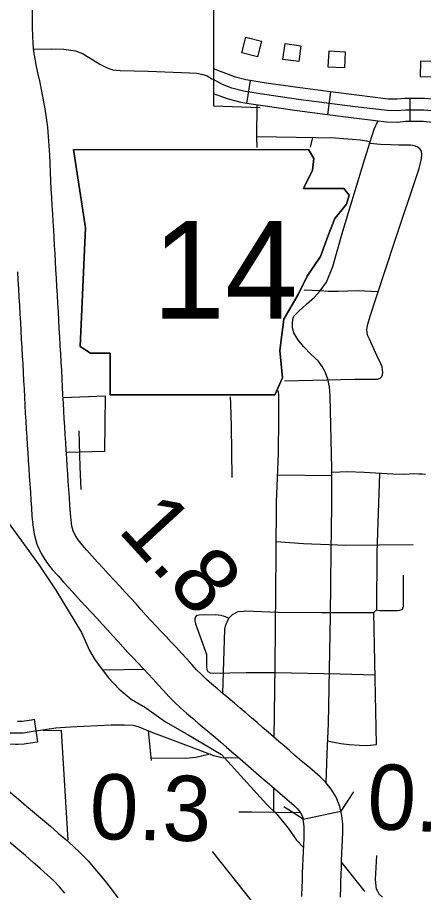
# Model space of a CAD drawing. Extents: x 1370130 to 1380143, y 377636 to 380256.
# Drawn here: x 1377398.1 to 1377471.8, y 379033.5 to 379192.2 of the extents above; entities that cross this region are included whole.
import ezdxf

# ---------------------------------------------------------------- set-up
doc = ezdxf.new("R2010")
doc.units = 0
for name, color, linetype in [('Level 10', 7, 'Continuous'), ('Level 15', 7, 'Continuous'), ('Level 21', 7, 'Continuous'), ('Level 31', 7, 'Continuous'), ('Level 32', 7, 'Continuous'), ('Level 33', 7, 'Continuous'), ('Level 34', 7, 'Continuous'), ('Level 35', 7, 'Continuous'), ('Level 37', 7, 'Continuous'), ('Level 48', 7, 'Continuous'), ('Level 49', 7, 'Continuous'), ('Level 56', 7, 'Continuous'), ('Level 6', 7, 'Continuous')]:
    doc.layers.add(name, color=color, linetype=linetype)

msp = doc.modelspace()

# ---------------------------------------------------------------- linework, layer by layer
at = {"layer": 'Level 10'}
for p, q in [((1377399.47, 379121.9), (1377399.48, 379121.89)), ((1377406.46, 379122.28), (1377406.46, 379122.27)), ((1377449.98, 379046.79), (1377456.82, 379048.25))]:
    msp.add_line(p, q, dxfattribs=at)
for points in [[(1377406.46, 379122.27), (1377406.39, 379123.72), (1377406.32, 379125.18), (1377406.24, 379126.67), (1377406.16, 379128.17), (1377406.08, 379129.68), (1377406, 379131.19), (1377405.91, 379132.73), (1377405.82, 379134.25), (1377405.73, 379135.77), (1377405.65, 379137.29), (1377405.56, 379138.8), (1377405.48, 379140.34), (1377405.39, 379141.88), (1377405.3, 379143.39), (1377405.21, 379144.93), (1377405.12, 379146.47), (1377405.03, 379147.96), (1377404.95, 379149.41), (1377404.87, 379150.84), (1377404.8, 379152.25), (1377404.72, 379153.69), (1377404.63, 379155.13), (1377404.54, 379156.57), (1377404.45, 379158.03), (1377404.36, 379159.51), (1377404.27, 379161.03), (1377404.17, 379162.54), (1377404.1, 379164.07), (1377404.04, 379165.64), (1377403.98, 379167.26), (1377403.9, 379168.9), (1377403.79, 379170.59), (1377403.62, 379172.3), (1377403.4, 379173.98), (1377403.14, 379175.61), (1377402.87, 379177.21), (1377402.57, 379178.81), (1377402.23, 379180.41), (1377401.87, 379181.91), (1377401.57, 379183.3), (1377401.32, 379184.67), (1377401.12, 379186.03), (1377400.99, 379187.4), (1377400.92, 379188.83), (1377400.89, 379190.36), (1377400.89, 379191.97), (1377400.89, 379193.65)], [(1377398.14, 379146.05), (1377398.22, 379144.53), (1377398.31, 379142.98), (1377398.41, 379141.47), (1377398.49, 379139.95), (1377398.57, 379138.42), (1377398.66, 379136.89), (1377398.74, 379135.37), (1377398.83, 379133.85), (1377398.92, 379132.33), (1377399.01, 379130.8), (1377399.09, 379129.3), (1377399.17, 379127.79), (1377399.25, 379126.3), (1377399.33, 379124.83), (1377399.4, 379123.36), (1377399.47, 379121.9)], [(1377399.48, 379121.89), (1377399.56, 379120.44), (1377399.64, 379118.98), (1377399.73, 379117.52), (1377399.83, 379116.1), (1377399.92, 379114.69), (1377400.01, 379113.27), (1377400.1, 379111.85), (1377400.19, 379110.43), (1377400.28, 379109), (1377400.38, 379107.55), (1377400.48, 379106.11), (1377400.58, 379104.68), (1377400.67, 379103.24), (1377400.77, 379101.78), (1377400.9, 379100.21), (1377401.15, 379098.52), (1377401.65, 379096.7), (1377402.45, 379094.96), (1377403.42, 379093.43), (1377404.46, 379092.08), (1377405.49, 379090.91), (1377406.49, 379089.8), (1377407.51, 379088.69), (1377408.52, 379087.58), (1377409.54, 379086.48), (1377410.56, 379085.38), (1377411.57, 379084.29), (1377412.56, 379083.23), (1377413.53, 379082.18), (1377414.47, 379081.14), (1377415.39, 379080.11), (1377416.32, 379079.08), (1377417.25, 379078.06), (1377418.17, 379077.06), (1377419.1, 379076.07), (1377420.01, 379075.1), (1377420.93, 379074.13), (1377421.85, 379073.16), (1377422.75, 379072.18), (1377423.67, 379071.17), (1377424.61, 379070.14), (1377425.59, 379069.08), (1377426.64, 379068.02), (1377427.73, 379066.99), (1377428.81, 379066.03), (1377429.88, 379065.1), (1377430.95, 379064.2), (1377432, 379063.32), (1377433.03, 379062.46), (1377434.04, 379061.6), (1377435.04, 379060.75), (1377436.05, 379059.89), (1377437.05, 379059.02), (1377438.04, 379058.17), (1377439.03, 379057.32), (1377440, 379056.48), (1377440.96, 379055.63), (1377441.92, 379054.8), (1377442.88, 379053.96), (1377443.84, 379053.13), (1377444.81, 379052.3), (1377445.77, 379051.51), (1377446.67, 379050.76), (1377447.52, 379050.04), (1377448.28, 379049.37), (1377448.91, 379048.73), (1377449.39, 379048.17), (1377449.69, 379047.67), (1377449.91, 379047.11), (1377449.98, 379046.79)], [(1377456.82, 379048.25), (1377456.64, 379049.12), (1377455.99, 379050.8), (1377455.07, 379052.28), (1377454.07, 379053.47), (1377453.09, 379054.46), (1377452.11, 379055.33), (1377451.16, 379056.13), (1377450.24, 379056.9), (1377449.32, 379057.66), (1377448.41, 379058.44), (1377447.47, 379059.25), (1377446.52, 379060.08), (1377445.56, 379060.91), (1377444.59, 379061.76), (1377443.6, 379062.61), (1377442.62, 379063.46), (1377441.62, 379064.32), (1377440.62, 379065.19), (1377439.6, 379066.07), (1377438.57, 379066.95), (1377437.53, 379067.82), (1377436.49, 379068.69), (1377435.46, 379069.56), (1377434.43, 379070.42), (1377433.42, 379071.3), (1377432.45, 379072.16), (1377431.54, 379073.02), (1377430.65, 379073.92), (1377429.76, 379074.88), (1377428.84, 379075.89), (1377427.91, 379076.91), (1377426.97, 379077.93), (1377426.03, 379078.93), (1377425.11, 379079.91), (1377424.19, 379080.87), (1377423.29, 379081.83), (1377422.4, 379082.79), (1377421.51, 379083.77), (1377420.6, 379084.79), (1377419.66, 379085.83), (1377418.69, 379086.9), (1377417.7, 379087.98), (1377416.7, 379089.06), (1377415.69, 379090.14), (1377414.68, 379091.23), (1377413.66, 379092.33), (1377412.66, 379093.42), (1377411.67, 379094.5), (1377410.72, 379095.56), (1377409.86, 379096.54), (1377409.15, 379097.45), (1377408.61, 379098.3), (1377408.25, 379099.1), (1377408.01, 379099.96), (1377407.86, 379101.02), (1377407.75, 379102.3), (1377407.66, 379103.69), (1377407.56, 379105.14), (1377407.46, 379106.6), (1377407.36, 379108.02), (1377407.27, 379109.45), (1377407.18, 379110.88), (1377407.09, 379112.29), (1377407, 379113.71), (1377406.91, 379115.12), (1377406.82, 379116.56), (1377406.72, 379117.99), (1377406.63, 379119.41), (1377406.55, 379120.84), (1377406.46, 379122.28)], [(1377456.75, 379032.66), (1377456.76, 379032.95), (1377456.79, 379034.23), (1377456.83, 379035.51), (1377456.87, 379036.8), (1377456.91, 379038.07), (1377456.96, 379039.32), (1377457.01, 379040.56), (1377457.07, 379041.81), (1377457.13, 379043.09), (1377457.17, 379044.44), (1377457.15, 379045.91), (1377456.99, 379047.47), (1377456.82, 379048.25)], [(1377449.75, 379032.77), (1377449.76, 379033.11), (1377449.79, 379034.41), (1377449.83, 379035.72), (1377449.87, 379037.02), (1377449.91, 379038.32), (1377449.96, 379039.6), (1377450.02, 379040.88), (1377450.08, 379042.14), (1377450.13, 379043.37), (1377450.17, 379044.49), (1377450.15, 379045.5), (1377450.06, 379046.39), (1377449.98, 379046.79)]]:
    msp.add_lwpolyline(points, dxfattribs=at)
at = {"layer": 'Level 15'}
for points in [[(1377387.89, 379059.09), (1377389.38, 379057.86), (1377390.87, 379056.62), (1377392.37, 379055.38), (1377393.86, 379054.14), (1377395.36, 379052.9), (1377396.85, 379051.66), (1377398.32, 379050.41), (1377399.78, 379049.18), (1377401.24, 379047.96), (1377402.69, 379046.74), (1377404.14, 379045.52), (1377405.55, 379044.29), (1377406.9, 379043.1), (1377408.23, 379041.91), (1377409.6, 379040.66), (1377410.95, 379039.27), (1377412.11, 379037.89), (1377413.21, 379036.58), (1377414.28, 379035.25), (1377415.33, 379033.92), (1377416.34, 379032.57)], [(1377406.74, 379033.39), (1377405.75, 379034.57), (1377404.72, 379035.63), (1377403.54, 379036.72), (1377402.26, 379037.86), (1377400.93, 379039.03), (1377399.58, 379040.21), (1377398.19, 379041.38), (1377396.74, 379042.59), (1377395.27, 379043.82), (1377393.81, 379045.06), (1377392.35, 379046.29), (1377390.88, 379047.52), (1377389.39, 379048.75), (1377387.9, 379049.99), (1377386.4, 379051.23), (1377384.92, 379052.46), (1377383.43, 379053.69)]]:
    msp.add_lwpolyline(points, dxfattribs=at)
at = {"layer": 'Level 21'}
for p, q in [((1377408.33, 379168.25), (1377410.46, 379154.04)), ((1377451.91, 379166.6), (1377450.93, 379168.23)), ((1377451.68, 379164.47), (1377451.91, 379166.6)), ((1377450.02, 379161.15), (1377451.68, 379164.47)), ((1377457.36, 379161.15), (1377450.02, 379161.15)), ((1377458.31, 379159.97), (1377457.36, 379161.15)), ((1377457.84, 379158.31), (1377458.31, 379159.97)), ((1377455.7, 379155.7), (1377457.84, 379158.31)), ((1377454.52, 379152.62), (1377455.7, 379155.7)), ((1377410.46, 379154.04), (1377409.52, 379132.49)), ((1377453.1, 379148.83), (1377454.52, 379152.62)), ((1377450.73, 379145.28), (1377453.1, 379148.83)), ((1377449.07, 379141.96), (1377450.73, 379145.28)), ((1377446.47, 379137.46), (1377449.07, 379141.96)), ((1377445.76, 379131.78), (1377446.47, 379137.46)), ((1377409.52, 379132.49), (1377411.41, 379131.31)), ((1377411.41, 379131.31), (1377414.97, 379131.31)), ((1377414.97, 379131.31), (1377414.97, 379123.73)), ((1377446.23, 379126.81), (1377445.76, 379131.78)), ((1377444.81, 379123.73), (1377446.23, 379126.81)), ((1377414.97, 379123.73), (1377444.81, 379123.73))]:
    msp.add_line(p, q, dxfattribs=at)
msp.add_lwpolyline([(1377408.33, 379168.25), (1377450.93, 379168.23)], dxfattribs=at)
at = {"layer": 'Level 31'}
msp.add_line((1377401.16, 379064.92), (1377401.75, 379060.76), dxfattribs=at)
for points in [[(1377398.14, 379064.57), (1377398.96, 379064.59), (1377400.66, 379064.85), (1377401.16, 379064.92)], [(1377383.43, 379062.74), (1377385.49, 379062.53), (1377388.41, 379062.49), (1377390.94, 379062.57), (1377395.24, 379062.49), (1377397.77, 379062.45), (1377399.15, 379062.49), (1377400.96, 379062.77), (1377401.46, 379062.84)], [(1377401.75, 379060.76), (1377401.27, 379060.69), (1377399.34, 379060.4), (1377398.26, 379060.37)], [(1377398.26, 379060.37), (1377397.78, 379060.35), (1377395.2, 379060.39), (1377390.95, 379060.47), (1377388.43, 379060.39), (1377386.24, 379060.42)]]:
    msp.add_lwpolyline(points, dxfattribs=at)
at = {"layer": 'Level 32'}
for p, q in [((1377440.36, 379180.75), (1377439.71, 379176.6)), ((1377454.94, 379178.69), (1377454.4, 379174.53)), ((1377469.36, 379177.5), (1377469.36, 379173.3))]:
    msp.add_line(p, q, dxfattribs=at)
for points in [[(1377440.36, 379180.75), (1377439.6, 379180.87), (1377437.68, 379181.36), (1377433.7, 379182.84), (1377433.69, 379178.36)], [(1377484.13, 379174.88), (1377477.62, 379175), (1377474.11, 379175.2), (1377471.88, 379175.4), (1377470.16, 379175.4), (1377468.52, 379175.4), (1377467.04, 379175.25), (1377465.26, 379175.3), (1377459.43, 379175.99), (1377449.15, 379177.33), (1377442.98, 379178.22), (1377439.17, 379178.81), (1377437.05, 379179.35), (1377435.32, 379180), (1377433.7, 379180.91)], [(1377454.94, 379178.69), (1377449.44, 379179.41), (1377443.29, 379180.29), (1377440.36, 379180.75)], [(1377439.71, 379176.6), (1377438.75, 379176.75), (1377436.42, 379177.35), (1377433.69, 379178.36)], [(1377469.36, 379177.5), (1377468.42, 379177.5), (1377466.97, 379177.35), (1377465.42, 379177.39), (1377459.69, 379178.07), (1377454.94, 379178.69)], [(1377454.4, 379174.53), (1377448.87, 379175.24), (1377442.67, 379176.14), (1377439.71, 379176.6)], [(1377479.53, 379172.87), (1377479.54, 379177.07), (1377477.7, 379177.1), (1377474.26, 379177.29), (1377471.98, 379177.5), (1377470.16, 379177.5), (1377469.36, 379177.5)], [(1377469.36, 379173.3), (1377468.63, 379173.3), (1377467.12, 379173.15), (1377465.11, 379173.2), (1377459.17, 379173.91), (1377454.4, 379174.53)], [(1377479.53, 379172.87), (1377477.54, 379172.9), (1377473.96, 379173.1), (1377471.79, 379173.3), (1377470.16, 379173.3), (1377469.36, 379173.3)]]:
    msp.add_lwpolyline(points, dxfattribs=at)
at = {"layer": 'Level 33'}
for points in [[(1377401.07, 379186.42), (1377404.29, 379186.52), (1377406.56, 379186.42), (1377408.69, 379186.13), (1377409.92, 379185.63), (1377411.35, 379184.79), (1377413.08, 379183.7), (1377414.42, 379183.06), (1377415.41, 379182.71), (1377416.79, 379182.57)], [(1377454.14, 379053.39), (1377454.35, 379058.65), (1377454.58, 379064.18), (1377454.94, 379083.67), (1377455.07, 379095.37), (1377455.16, 379103.65), (1377455.19, 379110.4), (1377454.87, 379123.53), (1377454.77, 379125.18), (1377454.48, 379126.57), (1377453.97, 379127.93), (1377453.45, 379128.87), (1377452.67, 379129.94), (1377451.41, 379131.07), (1377450.06, 379132.49), (1377448.99, 379133.78), (1377448.28, 379135.01), (1377448.05, 379135.92), (1377448.02, 379136.72), (1377448.09, 379137.47), (1377448.31, 379137.99), (1377449.18, 379138.92), (1377450.61, 379140.18), (1377452.06, 379141.48), (1377453.06, 379142.64), (1377454.19, 379144.19), (1377455.36, 379147), (1377457.2, 379153.44), (1377461.11, 379166.34), (1377462.88, 379171.9), (1377463.52, 379173.39)], [(1377441.66, 379168.62), (1377441.59, 379170.6), (1377455.84, 379170.38), (1377460.38, 379169.99), (1377461.48, 379169.8), (1377462.16, 379169.65)], [(1377446.59, 379126.32), (1377459.34, 379126.57), (1377462.79, 379126.57), (1377463.44, 379126.61), (1377463.93, 379126.78), (1377464.27, 379127.06), (1377464.4, 379127.4), (1377464.42, 379127.8), (1377464.37, 379128.24), (1377464.29, 379128.85), (1377464.09, 379129.4), (1377463.37, 379130.91), (1377462.01, 379133.83), (1377461.72, 379134.48), (1377461.57, 379135.05), (1377461.56, 379135.65), (1377461.69, 379136.55), (1377462.15, 379138.04), (1377463.28, 379141.5), (1377466.52, 379151.24), (1377471.01, 379164.77), (1377471.43, 379166.61), (1377471.5, 379167.39), (1377471.43, 379167.94), (1377471.21, 379168.29), (1377470.79, 379168.65), (1377470.37, 379168.87), (1377469.88, 379168.97), (1377469.43, 379169), (1377468.59, 379169), (1377467.33, 379169), (1377465.88, 379169.07), (1377464, 379169.17), (1377462.06, 379169.34)], [(1377463.6, 379142.44), (1377459.84, 379142.6), (1377456.31, 379142.5), (1377454.5, 379142.5), (1377453.02, 379142.6)], [(1377444.71, 379061.65), (1377444.92, 379074.61), (1377445.05, 379094.91), (1377445.15, 379104.28), (1377445.5, 379113.14), (1377445.57, 379119.61), (1377445.57, 379123.81), (1377445.47, 379124.54)], [(1377406.41, 379123.3), (1377414.07, 379123.57)], [(1377414.07, 379123.57), (1377413.92, 379113.48), (1377407.02, 379113.31)], [(1377436.72, 379123.42), (1377436.81, 379122.13), (1377436.92, 379118.07), (1377437.02, 379108.76)], [(1377455.19, 379109.06), (1377445.34, 379109.17)], [(1377450.03, 379096.77), (1377457.71, 379096.51)], [(1377435.4, 379069.6), (1377435.76, 379081.26), (1377435.95, 379082.06), (1377436.49, 379083.27), (1377437.18, 379083.9), (1377438.21, 379084.47), (1377439.16, 379084.54), (1377439.45, 379084.57)], [(1377453.28, 379084.3), (1377459.08, 379084.29)], [(1377421.11, 379073.96), (1377413.71, 379073.84)], [(1377444.9, 379073.42), (1377456.71, 379073.16)], [(1377401.46, 379062.84), (1377405.11, 379063.36), (1377407.71, 379063.56), (1377415.13, 379063.92), (1377417.54, 379063.92), (1377419.15, 379063.84), (1377420.18, 379063.56), (1377422.35, 379062.65), (1377430.09, 379059.73), (1377433.68, 379058.35), (1377435.22, 379057.99), (1377436.91, 379057.95), (1377438.21, 379058.02)], [(1377422.43, 379057.47), (1377421.92, 379062.83)], [(1377449.52, 379047.95), (1377440.62, 379048.06), (1377438.32, 379048.06)]]:
    msp.add_lwpolyline(points, dxfattribs=at)
at = {"layer": 'Level 34'}
for points in [[(1377416.79, 379182.57), (1377421.88, 379182.47), (1377429.44, 379182.17), (1377430.67, 379182.07), (1377431.86, 379181.82), (1377432.55, 379181.58), (1377433.39, 379181.08), (1377433.7, 379180.91)], [(1377441.59, 379170.6), (1377441.6, 379176.31)], [(1377451.29, 379168.66), (1377451.76, 379170.44)], [(1377453.06, 379142.64), (1377450.13, 379142.76)], [(1377409.29, 379117.23), (1377409.45, 379110.67), (1377409.66, 379106.61)], [(1377472.17, 379109.28), (1377471.57, 379109.36), (1377470.95, 379109.4), (1377470.06, 379109.42), (1377468.43, 379109.33), (1377466.23, 379109.37), (1377461.06, 379109.67), (1377457.96, 379109.77), (1377456.63, 379109.72), (1377455.23, 379109.65)], [(1377459.08, 379084.29), (1377462.83, 379084.29), (1377463.36, 379084.76), (1377463.39, 379095.19), (1377463.9, 379109.51)], [(1377445.07, 379097.19), (1377450.03, 379096.77)], [(1377457.71, 379096.51), (1377469.96, 379096.61)], [(1377463.36, 379084.76), (1377463.91, 379084.67), (1377467.07, 379084.65), (1377467.54, 379084.7), (1377467.84, 379084.81), (1377468, 379084.97), (1377468.11, 379085.16), (1377468.16, 379085.45), (1377468.16, 379091.07)], [(1377439.45, 379084.57), (1377445.43, 379084.35), (1377453.28, 379084.3)], [(1377463.3, 379060.36), (1377463.18, 379066.39), (1377462.83, 379084.29)], [(1377436.49, 379083.27), (1377435.68, 379083.57), (1377435.1, 379083.76), (1377434.02, 379083.86), (1377431.04, 379083.79), (1377430.59, 379083.67), (1377430.43, 379083.51), (1377430.3, 379083.15), (1377430.3, 379082.77), (1377430.43, 379082.26), (1377432.26, 379077.23), (1377432.42, 379076.65), (1377432.42, 379076.05), (1377432.42, 379074.41), (1377432.48, 379073.96), (1377432.7, 379073.58), (1377433.12, 379073.36), (1377433.73, 379073.29), (1377439.65, 379073.42), (1377444.9, 379073.42)], [(1377456.71, 379073.16), (1377463.05, 379072.97)], [(1377454.45, 379060.99), (1377455.21, 379060.81), (1377456.79, 379060.53), (1377458.35, 379060.33), (1377460.17, 379060.21), (1377461.63, 379060.18), (1377463.3, 379060.36)], [(1377433.09, 379058.58), (1377432.05, 379058.35), (1377430.5, 379058), (1377428.66, 379057.83), (1377422.39, 379057.87)], [(1377444.65, 379048.01), (1377444.64, 379052.44)], [(1377464.38, 379032.69), (1377463.81, 379033.16), (1377463.29, 379034.14), (1377463.12, 379035.87), (1377463.34, 379040.23)]]:
    msp.add_lwpolyline(points, dxfattribs=at)
at = {"layer": 'Level 35'}
for points in [[(1377378.37, 379128.9), (1377378.37, 379127.5), (1377377.85, 379125.47), (1377377.64, 379123.69), (1377377.69, 379122.69), (1377378.1, 379120.42), (1377379.07, 379117.97), (1377381.76, 379112.75), (1377383.92, 379110.36), (1377388.16, 379106.38), (1377388.9, 379105.83), (1377392.33, 379104.14), (1377393.7, 379103.24), (1377396.42, 379100.63), (1377402.09, 379092.84), (1377405.07, 379088.35), (1377409.75, 379080.65), (1377411.22, 379077.37), (1377412.22, 379075.62), (1377414.67, 379072.47), (1377416.59, 379070.41), (1377418.74, 379068.55), (1377420.95, 379067.3), (1377421.19, 379067.21)], [(1377421.19, 379067.21), (1377425, 379064.44), (1377428.91, 379062.22), (1377435.13, 379058.52), (1377443.31, 379049.53), (1377445.17, 379047.72), (1377447.25, 379045.21), (1377448.75, 379043.02), (1377450.05, 379041.68)], [(1377456.94, 379038.93), (1377460.97, 379033.85), (1377461.14, 379033.68)]]:
    msp.add_lwpolyline(points, dxfattribs=at)
at = {"layer": 'Level 37'}
for points in [[(1377459.11, 379051.78), (1377456.82, 379048.25)], [(1377449.98, 379046.79), (1377446.45, 379049.07)]]:
    msp.add_lwpolyline(points, dxfattribs=at)
at = {"layer": 'Level 48'}
msp.add_lwpolyline([(1377433.46, 379040.94), (1377440.91, 379031.61), (1377442.1, 379020.62)], dxfattribs=at)
at = {"layer": 'Level 49'}
for p, q in [((1377410.46, 379154.04), (1377408.33, 379168.25)), ((1377451.68, 379164.47), (1377450.02, 379161.15)), ((1377450.02, 379161.15), (1377457.36, 379161.15)), ((1377457.84, 379158.31), (1377455.7, 379155.7)), ((1377455.7, 379155.7), (1377454.52, 379152.62)), ((1377409.52, 379132.49), (1377410.46, 379154.04)), ((1377454.52, 379152.62), (1377453.1, 379148.83)), ((1377453.1, 379148.83), (1377450.73, 379145.28)), ((1377450.73, 379145.28), (1377449.07, 379141.96)), ((1377449.07, 379141.96), (1377446.47, 379137.46)), ((1377446.47, 379137.46), (1377445.76, 379131.78)), ((1377411.41, 379131.31), (1377409.52, 379132.49)), ((1377445.76, 379131.78), (1377446.23, 379126.81)), ((1377446.23, 379126.81), (1377444.81, 379123.73)), ((1377444.81, 379123.73), (1377414.97, 379123.73))]:
    msp.add_line(p, q, dxfattribs=at)
for points in [[(1377408.33, 379168.25), (1377450.93, 379168.23)], [(1377450.93, 379168.23), (1377451.91, 379166.6), (1377451.68, 379164.47)], [(1377457.36, 379161.15), (1377458.31, 379159.97), (1377457.84, 379158.31)], [(1377414.97, 379123.73), (1377414.97, 379131.31), (1377411.41, 379131.31)]]:
    msp.add_lwpolyline(points, dxfattribs=at)
at = {"layer": 'Level 56'}
for points in [[(1377442.41, 379187.87), (1377441.68, 379185.05), (1377438.85, 379185.79), (1377439.59, 379188.61)], [(1377446.7, 379187.47), (1377449.58, 379187.06), (1377449.17, 379184.17), (1377446.28, 379184.58)], [(1377457.62, 379185.94), (1377457.45, 379183.03), (1377454.53, 379183.2), (1377454.7, 379186.11)], [(1377471.26, 379181.42), (1377471.33, 379184.34), (1377474.25, 379184.26), (1377474.18, 379181.35)]]:
    msp.add_lwpolyline(points, close=True, dxfattribs=at)
at = {"layer": 'Level 6'}
for points in [[(1377433.72, 379203.81), (1377433.69, 379176.13), (1377442.19, 379175.83)], [(1377407.32, 379043.02), (1377406.15, 379062.87), (1377402.81, 379062.85)]]:
    msp.add_lwpolyline(points, dxfattribs=at)

# ---------------------------------------------------------------- texts
at = {"layer": 'Level 21'}
msp.add_text('14', height=17.741, dxfattribs=at).set_placement((1377422.61, 379137.55))
at = {"layer": 'Level 48'}
for s, rotation, p in [('1.8', 312.536, (1377416.14, 379099.14)), ('0.2', 357.1364, (1377461.39, 379045.1)), ('0.3', 358.8021, (1377411.17, 379043.23))]:
    msp.add_text(s, height=11.827, rotation=rotation, dxfattribs=at).set_placement(p)

doc.saveas('drawing.dxf')
